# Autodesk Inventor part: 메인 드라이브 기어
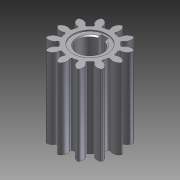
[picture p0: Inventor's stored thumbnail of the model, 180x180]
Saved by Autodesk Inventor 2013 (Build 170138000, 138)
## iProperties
Created: 2013-07
Part Number: 메인 드라이브 기어
Document SubType Name: Modeling
Designer: 한국산업디자인학원
Density: 1 g/cm^3
Mass: 93.0555 g
Surface Area: 295.478 cm^2
Volume: 93.0555 cm^3
Material: 강철, 탄소
변환 표준: STEP AP214IS
파일 이름: C:\Documents and Settings\?댁씪諛곗?1\諛뷀깢 ?붾㈃\2013-07-27 ?덉긽臾몄젣\媛?몄삩 援ъ꽦?붿냼\留ㅺ컻蹂??MZ)?섏젙?섎㈃ ?먮룞? 留뚮뱾?댁????ㅽ띁湲곗뼱.stp
전처리기: Build: 223b, Release: 2010 RTM - Date: Sat 02/14/2009
전송 단위: 밀리미터
불확실성: 0.01
Author: 한국산업디자인학원
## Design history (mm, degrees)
sketch "스케치1"
  geometry: A1 r 6 centre (-2.816, 23.011) between (2.462, 20.157) and (0.524, 27.995) reference; A2 r 28 centre (0, 0) between (0.524, 27.995) and (-0.524, 27.995) reference; A3 r 6 centre (2.816, 23.011) between (-0.524, 27.995) and (-2.462, 20.157) reference; A4 r 0.972 centre (-3.318, 19.695) between (-3.156, 18.736) and (-2.462, 20.157) reference; A5 r 19 centre (0, 0) between (-3.156, 18.736) and (-6.635, 17.804) reference; A6 r 0.972 centre (-6.974, 18.715) between (-7.946, 18.688) and (-6.635, 17.804) reference; A7 r 6 centre (-13.944, 18.52) between (-7.946, 18.688) and (-13.544, 24.506) reference; A8 r 28 centre (0, 0) between (-13.544, 24.506) and (-14.451, 23.983) reference; A9 r 6 centre (-9.067, 21.336) between (-14.451, 23.983) and (-12.211, 16.226) reference; A10 r 0.972 centre (-12.721, 15.397) between (-12.101, 14.648) and (-12.211, 16.226) reference; A11 r 19 centre (0, 0) between (-12.101, 14.648) and (-14.648, 12.101) reference; A12 r 0.972 centre (-15.397, 12.721) between (-16.226, 12.211) and (-14.648, 12.101) reference; A13 r 6 centre (-21.336, 9.067) between (-16.226, 12.211) and (-23.983, 14.451) reference; A14 r 28 centre (0, 0) between (-23.983, 14.451) and (-24.506, 13.544) reference; A15 r 6 centre (-18.52, 13.944) between (-24.506, 13.544) and (-18.688, 7.946) reference; A16 r 0.972 centre (-18.715, 6.974) between (-17.804, 6.635) and (-18.688, 7.946) reference; A17 r 19 centre (0, 0) between (-17.804, 6.635) and (-18.736, 3.156) reference; A18 r 0.972 centre (-19.695, 3.318) between (-20.157, 2.462) and (-18.736, 3.156) reference; A19 r 6 centre (-23.011, -2.816) between (-20.157, 2.462) and (-27.995, 0.524) reference; A20 r 28 centre (0, 0) between (-27.995, 0.524) and (-27.995, -0.524) reference; A21 r 6 centre (-23.011, 2.816) between (-27.995, -0.524) and (-20.157, -2.462) reference; A22 r 0.972 centre (-19.695, -3.318) between (-18.736, -3.156) and (-20.157, -2.462) reference; A23 r 19 centre (0, 0) between (-18.736, -3.156) and (-17.804, -6.635) reference; A24 r 0.972 centre (-18.715, -6.974) between (-18.688, -7.946) and (-17.804, -6.635) reference; A25 r 6 centre (-18.52, -13.944) between (-18.688, -7.946) and (-24.506, -13.544) reference; A26 r 28 centre (0, 0) between (-24.506, -13.544) and (-23.983, -14.451) reference; A27 r 6 centre (-21.336, -9.067) between (-23.983, -14.451) and (-16.226, -12.211) reference; A28 r 0.972 centre (-15.397, -12.721) between (-14.648, -12.101) and (-16.226, -12.211) reference; A29 r 19 centre (0, 0) between (-14.648, -12.101) and (-12.101, -14.648) reference; A30 r 0.972 centre (-12.721, -15.397) between (-12.211, -16.226) and (-12.101, -14.648) reference; A31 r 6 centre (-9.067, -21.336) between (-12.211, -16.226) and (-14.451, -23.983) reference; A32 r 28 centre (0, 0) between (-14.451, -23.983) and (-13.544, -24.506) reference; A33 r 6 centre (-13.944, -18.52) between (-13.544, -24.506) and (-7.946, -18.688) reference; A34 r 0.972 centre (-6.974, -18.715) between (-6.635, -17.804) and (-7.946, -18.688) reference; A35 r 19 centre (0, 0) between (-6.635, -17.804) and (-3.156, -18.736) reference; A36 r 0.972 centre (-3.318, -19.695) between (-2.462, -20.157) and (-3.156, -18.736) reference; A37 r 6 centre (2.816, -23.011) between (-2.462, -20.157) and (-0.524, -27.995) reference; A38 r 28 centre (0, 0) between (-0.524, -27.995) and (0.524, -27.995) reference; A39 r 6 centre (-2.816, -23.011) between (0.524, -27.995) and (2.462, -20.157) reference; A40 r 0.972 centre (3.318, -19.695) between (3.156, -18.736) and (2.462, -20.157) reference; A41 r 19 centre (0, 0) between (3.156, -18.736) and (6.635, -17.804) reference; A42 r 0.972 centre (6.974, -18.715) between (7.946, -18.688) and (6.635, -17.804) reference; A43 r 6 centre (13.944, -18.52) between (7.946, -18.688) and (13.544, -24.506) reference; A44 r 28 centre (0, 0) between (13.544, -24.506) and (14.451, -23.983) reference; A45 r 6 centre (9.067, -21.336) between (14.451, -23.983) and (12.211, -16.226) reference; A46 r 0.972 centre (12.721, -15.397) between (12.101, -14.648) and (12.211, -16.226) reference; A47 r 19 centre (0, 0) between (12.101, -14.648) and (14.648, -12.101) reference; A48 r 0.972 centre (15.397, -12.721) between (16.226, -12.211) and (14.648, -12.101) reference; A49 r 6 centre (21.336, -9.067) between (16.226, -12.211) and (23.983, -14.451) reference; A50 r 28 centre (0, 0) between (23.983, -14.451) and (24.506, -13.544) reference; A51 r 6 centre (18.52, -13.944) between (24.506, -13.544) and (18.688, -7.946) reference; A52 r 0.972 centre (18.715, -6.974) between (17.804, -6.635) and (18.688, -7.946) reference; A53 r 19 centre (0, 0) between (17.804, -6.635) and (18.736, -3.156) reference; A54 r 0.972 centre (19.695, -3.318) between (20.157, -2.462) and (18.736, -3.156) reference; A55 r 6 centre (23.011, 2.816) between (20.157, -2.462) and (27.995, -0.524) reference; A56 r 28 centre (0, 0) between (27.995, -0.524) and (27.995, 0.524) reference; A57 r 6 centre (23.011, -2.816) between (27.995, 0.524) and (20.157, 2.462) reference; A58 r 0.972 centre (19.695, 3.318) between (18.736, 3.156) and (20.157, 2.462) reference; A59 r 19 centre (0, 0) between (18.736, 3.156) and (17.804, 6.635) reference; A60 r 0.972 centre (18.715, 6.974) between (18.688, 7.946) and (17.804, 6.635) reference; A61 r 6 centre (18.52, 13.944) between (18.688, 7.946) and (24.506, 13.544) reference; A62 r 28 centre (0, 0) between (24.506, 13.544) and (23.983, 14.451) reference; A63 r 6 centre (21.336, 9.067) between (23.983, 14.451) and (16.226, 12.211) reference; A64 r 0.972 centre (15.397, 12.721) between (14.648, 12.101) and (16.226, 12.211) reference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; 1 further point
extrude "돌출1" new body sketch "스케치1" stored distance "d0" = 70; taper "d1" = 0 deg
sketch "스케치2"
  geometry: L1 (-3, 10.062)-(-3, 13.3); L2 (-3, 13.3)-(3, 13.3); L3 (3, 13.3)-(3, 10.062); A1 r 10.5 centre (0, 0) between (-3, 10.062) and (3, 10.062); 1 further point
  constraints: 6 end point, 2 parallel, 2 point on circle, 1 centre point, 1 coincident, 1 perpendicular, 1 vertical
  dimensions: "d2" = 21 diameter of A1; "d3" = 6 distance of L1.end L2.end; "d4" = 23.8 dimension on A1 L2 (computed from d2)
extrude "돌출2" cut sketch "스케치2" stored distance "d5" = 10; taper "d6" = 0 deg
sketch "스케치3"
  geometry: C1 r 14 at (0, 0) reference; C2 r 15 at (0, 0); 1 further point
  constraints: 1 centre point
  dimensions: "d10" = 1 radial gap between concentric circles of C2 C1
extrude "돌출3" cut sketch "스케치3" distance "d11" = 1; taper "d12" = 0 deg
chamfer "모따기2" distance "d13" = 1; stored, may be unused: second distance "d14" = 2, angle "d15" = 45 deg
node "솔리드4"
mirror "대칭1"
node "투영된 루프1"
node "솔리드2"
node "참조1"
